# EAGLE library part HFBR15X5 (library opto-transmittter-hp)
OPTO TRANSMITTER
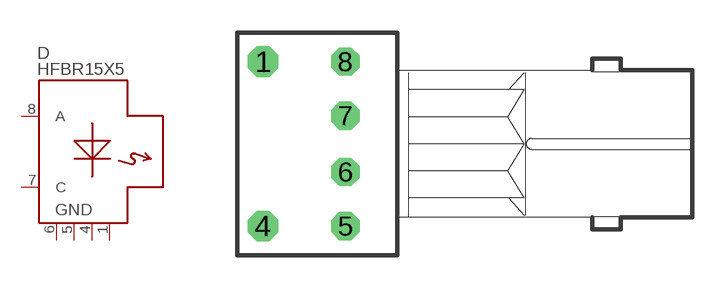
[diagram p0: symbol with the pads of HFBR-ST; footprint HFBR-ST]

Designator prefix D

## HFBR15X5  [HFBR-ST]
1  1  pas
4  4  pas
5  GND  pas
6  GND  pas
7  C  out
8  A  out

## Footprint HFBR-ST (pad centres in mm)
OPTO TRANSMITTER
drill 0.9 octagon: 1 -2.5,3.8; 4 -2.5,-3.8
drill 0.8 octagon: 5 1.3,-3.8; 6 1.3,-1.3; 7 1.3,1.3; 8 1.3,3.8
